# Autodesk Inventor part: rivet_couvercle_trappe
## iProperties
Created: 2011-01
Part Number: rivet_couvercle_trappe
Document SubType Name: Modeling
Designer: eric
Density: 1 g/cm^3
Mass: 0.164572 g
Surface Area: 3.29475 cm^2
Volume: 0.164572 cm^3
Author: eric
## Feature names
1. Base1
